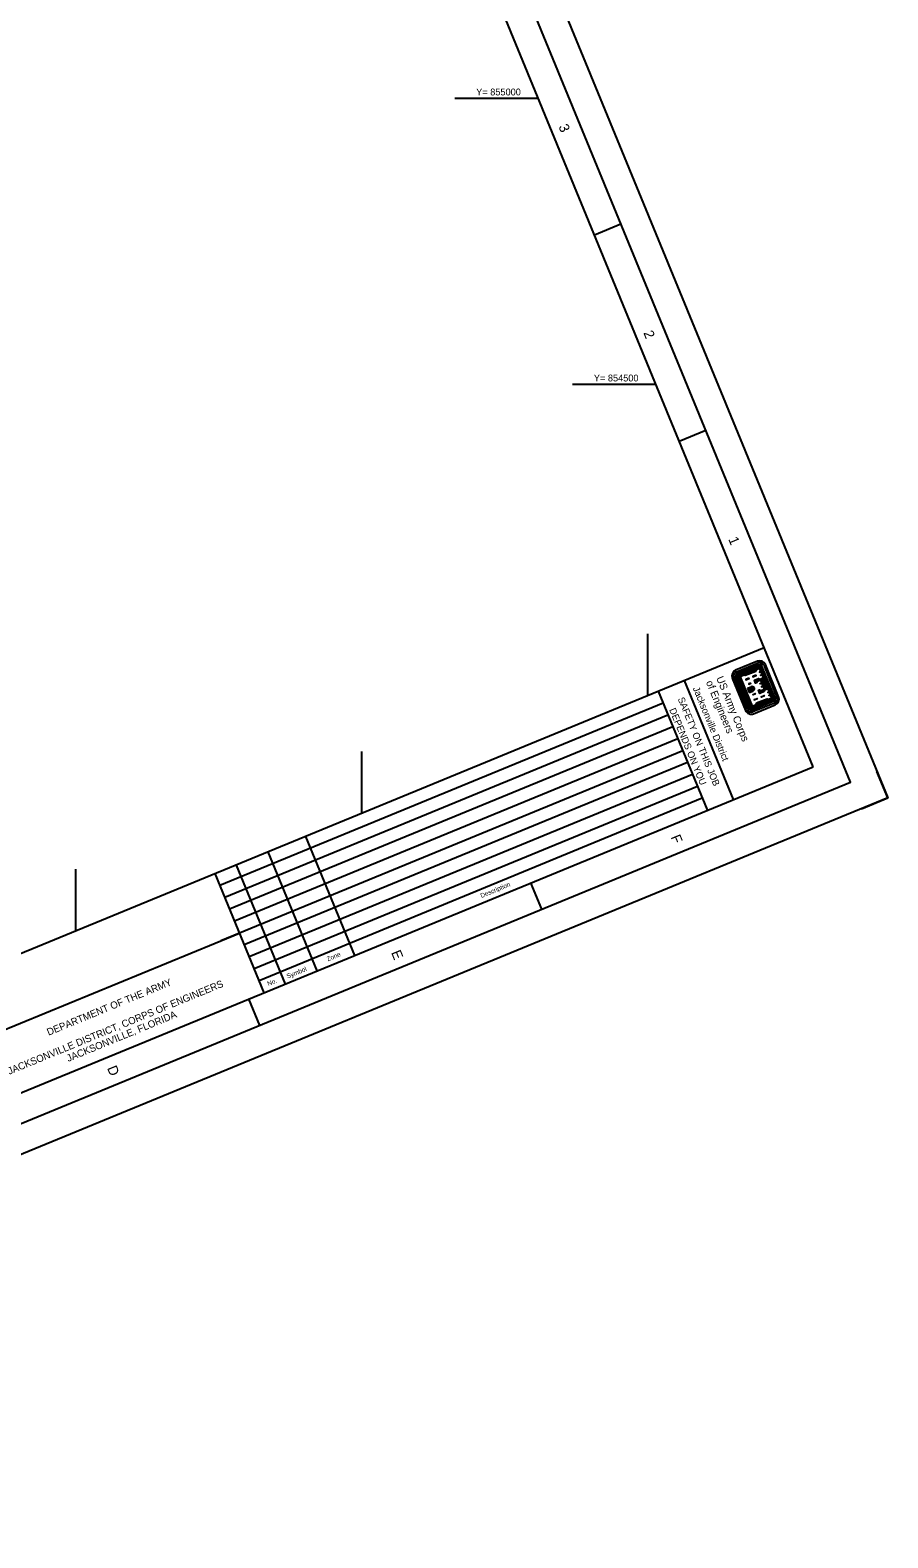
# Model space of a CAD drawing. Extents: x 579601 to 584420, y 852483 to 857846.
# Drawn here: x 582920 to 584420, y 852483 to 855119 of the extents above; entities that cross this region are included whole.
import ezdxf

# ---------------------------------------------------------------- set-up
doc = ezdxf.new("R2010")
doc.units = 0
for name, color, linetype in [('G-ANNO-NPLT', 7, 'Continuous'), ('G-ANNO-TEXT-LOGO', 7, 'Continuous'), ('G-ANNO-TEXT-TTLB', 7, 'Continuous'), ('G-ANNO-TTLB', 7, 'Continuous'), ('V-TOPO-COOR-STAT', 7, 'Continuous')]:
    doc.layers.add(name, color=color, linetype=linetype)

msp = doc.modelspace()

# ---------------------------------------------------------------- linework, layer by layer
at = {"layer": 'G-ANNO-NPLT'}
msp.add_lwpolyline([(582745.7, 857846.1), (584419.8, 853777), (581275.5, 852483.4), (579601.4, 856552.5)], close=True, dxfattribs=at)
msp.add_lwpolyline([(584373.5, 853758), (584419.8, 853777), (584400.7, 853823.2)], dxfattribs=at)
at = {"layer": 'G-ANNO-TEXT-LOGO'}
for p, q in [((584191.7, 854015.8), (584153.7, 854000.2)), ((584155, 853997.2), (584192.9, 854012.8)), ((584194.2, 854009.6), (584156.3, 853994)), ((584194.5, 854008.8), (584156.6, 853993.2)), ((584194.8, 854008), (584156.9, 853992.4)), ((584195.2, 854007.2), (584157.3, 853991.6)), ((584195.5, 854006.4), (584157.6, 853990.8)), ((584195.9, 854005.5), (584158.2, 853990.1)), ((584196.2, 854004.8), (584159.4, 853989.7)), ((584188.4, 854000.8), (584169, 853992.9)), ((584187.9, 853999.7), (584170.2, 853992.4)), ((584219.4, 853949.9), (584196.3, 854006.1)), ((584220.2, 853950.3), (584197.1, 854006.5)), ((584221, 853950.6), (584197.9, 854006.8)), ((584221.8, 853950.9), (584198.7, 854007.1)), ((584222.6, 853951.2), (584199.5, 854007.5)), ((584202.7, 854008.8), (584225.8, 853952.5)), ((584228.8, 853953.8), (584205.6, 854010)), ((584147.8, 853986.2), (584171, 853930)), ((584174, 853931.2), (584150.9, 853987.5)), ((584177.2, 853932.6), (584154.1, 853988.8)), ((584178, 853932.9), (584154.8, 853989.1)), ((584178.8, 853933.2), (584155.7, 853989.4)), ((584179.6, 853933.6), (584156.5, 853989.8)), ((584180.4, 853933.9), (584157.3, 853990.1)), ((584181.1, 853934.6), (584158.2, 853990.1)), ((584181.6, 853935.6), (584159.4, 853989.7)), ((584174.4, 853968.6), (584180.6, 853971.1)), ((584198.8, 853984.3), (584205.8, 853967.1)), ((584199.6, 853984.7), (584206.7, 853967.5)), ((584200.3, 853985), (584207.4, 853967.8)), ((584201.2, 853985.3), (584208.2, 853968.1)), ((584202, 853985.7), (584209.1, 853968.5)), ((584202.7, 853986), (584209.8, 853968.8)), ((584203.6, 853986.3), (584210.6, 853969.1)), ((584174.4, 853968.6), (584177.5, 853961.2)), ((584174.7, 853967.9), (584180.9, 853970.4)), ((584175.1, 853967), (584181.3, 853969.6)), ((584175.4, 853966.2), (584181.6, 853968.7)), ((584175.7, 853965.5), (584181.9, 853968)), ((584176.2, 853964.3), (584182.4, 853966.9)), ((584176.5, 853963.6), (584182.7, 853966.2)), ((584176.8, 853962.8), (584183, 853965.3)), ((584177.2, 853961.9), (584183.4, 853964.5)), ((584177.5, 853961.2), (584183.7, 853963.7)), ((584218.7, 853950.1), (584181.1, 853934.6)), ((584219, 853949.2), (584181.1, 853933.6)), ((584219.4, 853948.4), (584181.5, 853932.8)), ((584218.4, 853950.8), (584181.6, 853935.6)), ((584219.7, 853947.6), (584181.8, 853932)), ((584220, 853946.8), (584182.1, 853931.2)), ((584220.4, 853946), (584182.5, 853930.4)), ((584210, 853948.1), (584190.8, 853940.2)), ((584208.9, 853948.6), (584191.2, 853941.4)), ((584221.7, 853942.8), (584183.8, 853927.2)), ((584185, 853924.2), (584222.9, 853939.8))]:
    msp.add_line(p, q, dxfattribs=at)
for points in [[(584196.4, 854004.2), (584189.1, 854001.1), (584188.2, 853998.9), (584170.6, 853991.7), (584168.2, 853992.5), (584160.2, 853989.2), (584181.9, 853936.5), (584189.9, 853939.8), (584190.9, 853942.2), (584208.6, 853949.5), (584210.8, 853948.4), (584218.1, 853951.4), (584215.3, 853958.4), (584213.1, 853963.7), (584211, 853968.7), (584203.7, 853965.7), (584202.9, 853963.3), (584196.4, 853960.7), (584194.8, 853964.5), (584195.4, 853964.8), (584197.8, 853963.8), (584205, 853966.8), (584202.1, 853973.7), (584199.9, 853979.1), (584197.9, 853984), (584190.7, 853981), (584189.7, 853978.7), (584189.1, 853978.4), (584187.5, 853982.3), (584194, 853985), (584196.2, 853983.9), (584203.5, 853987), (584200.7, 853993.9), (584198.5, 853999.3), (584196.4, 854004.2)], [(584195.9, 854003.1), (584189.8, 854000.6), (584188.8, 853998.2), (584170.5, 853990.7), (584168.2, 853991.7), (584161.3, 853988.8), (584182.4, 853937.6), (584189.3, 853940.4), (584190.2, 853942.9), (584208.5, 853950.4), (584210.9, 853949.3), (584217, 853951.8), (584214.9, 853956.8), (584212.1, 853955.7), (584211.9, 853956.1), (584214.8, 853957.3), (584212.7, 853962.2), (584209.9, 853961), (584209.7, 853961.4), (584212.6, 853962.6), (584210.5, 853967.6), (584204.4, 853965), (584203.4, 853962.7), (584196, 853959.6), (584193.7, 853965), (584195.5, 853965.7), (584197.9, 853964.7), (584204, 853967.2), (584201.9, 853972.2), (584199, 853971), (584198.9, 853971.4), (584201.8, 853972.6), (584199.7, 853977.6), (584196.8, 853976.4), (584196.6, 853976.9), (584199.5, 853978.1), (584197.5, 853983), (584191.4, 853980.4), (584190.4, 853978.1), (584188.6, 853977.4), (584186.4, 853982.7), (584193.9, 853985.8), (584196.3, 853984.8), (584202.4, 853987.3), (584200.4, 853992.3), (584197.5, 853991.1), (584197.3, 853991.5), (584200.2, 853992.7), (584198.1, 853997.7), (584195.3, 853996.5), (584195.1, 853996.9), (584198, 853998.1), (584195.9, 854003.1)], [(584176.8, 853986.4), (584171.4, 853984.1), (584171.6, 853983.6), (584177.1, 853985.8), (584176.8, 853986.4)], [(584180.3, 853977.8), (584176.6, 853976.3), (584176.7, 853975.8), (584180.5, 853977.4), (584180.3, 853977.8)], [(584189.1, 853991.4), (584183.8, 853989.2), (584184, 853988.7), (584189.4, 853990.9), (584189.1, 853991.4)], [(584194.6, 853983.7), (584193.9, 853984), (584188.7, 853981.8), (584189.4, 853980.1), (584190.1, 853981.7), (584194.7, 853983.7)], [(584188.2, 853958.8), (584184.4, 853957.2), (584184.2, 853957.7), (584188, 853959.3), (584188.2, 853958.8)], [(584191.6, 853950.4), (584186.2, 853948.1), (584186, 853948.6), (584191.5, 853950.8), (584191.6, 853950.4)], [(584202.4, 853964.7), (584202.2, 853964), (584196.9, 853961.8), (584196.2, 853963.5), (584197.9, 853962.9), (584202.5, 853964.8)], [(584203.9, 853955.4), (584198.6, 853953.2), (584198.4, 853953.7), (584203.8, 853955.9), (584203.9, 853955.4)]]:
    msp.add_lwpolyline(points, dxfattribs=at)
for centre, major_axis, start_param, end_param in [((584157.8, 853990.3), (-4.08, 9.91), 6.28317, 7.853966), ((584157.8, 853990.3), (-2.85, 6.93), 6.28317, 7.853966), ((584195.7, 854005.9), (4.08, -9.91), 1.57078, 3.141576), ((584195.7, 854005.9), (2.85, -6.93), 1.57078, 3.141576), ((584195.7, 854005.9), (1.53, -3.72), 1.57078, 3.141576), ((584195.7, 854005.9), (1.2, -2.91), 1.57078, 3.141576), ((584195.7, 854005.9), (0.87, -2.11), 1.57078, 3.141576), ((584195.7, 854005.9), (0.54, -1.31), 1.57078, 3.141576), ((584195.7, 854005.9), (0.208, -0.505), 1.57078, 3.141576), ((584157.8, 853990.3), (-1.53, 3.72), 6.28317, 7.853966), ((584157.8, 853990.3), (-1.2, 2.91), 6.28317, 7.853966), ((584157.8, 853990.3), (-0.87, 2.11), 6.28317, 7.853966), ((584157.8, 853990.3), (-0.54, 1.31), 6.28317, 7.853966), ((584157.8, 853990.3), (-0.208, 0.505), 6.28317, 7.853966), ((584182.3, 853965.9), (-2.11, 5.14), 4.985832, 6.214359), ((584182.3, 853965.9), (-1.78, 4.33), 4.947465, 6.21436), ((584182.3, 853965.9), (-1.45, 3.53), 4.947465, 6.21436), ((584182.3, 853965.9), (-1.12, 2.73), 4.947465, 6.21436), ((584182.3, 853965.9), (-0.79, 1.92), 4.947465, 6.214359), ((584181.1, 853968.7), (0.79, -1.92), 0.068794, 1.335689), ((584181.1, 853968.7), (1.12, -2.73), 0.068794, 1.335689), ((584181.1, 853968.7), (1.45, -3.53), 0.068795, 1.335689), ((584181.1, 853968.7), (1.78, -4.33), 0.068795, 1.335689), ((584181.1, 853968.7), (2.11, -5.14), 0.068795, 1.29842), ((584218.8, 853949.7), (0.208, -0.505), 6.283169, 7.853965), ((584218.8, 853949.7), (0.54, -1.31), 6.283169, 7.853965), ((584218.8, 853949.7), (0.87, -2.11), 6.283169, 7.853965), ((584218.8, 853949.7), (1.2, -2.91), 6.283169, 7.853965), ((584218.8, 853949.7), (1.53, -3.72), 6.283169, 7.853965), ((584218.8, 853949.7), (2.85, -6.93), 6.28317, 7.853966), ((584218.8, 853949.7), (4.08, -9.91), 6.283169, 7.853965), ((584180.9, 853934.1), (4.08, -9.91), 4.712373, 6.28317), ((584180.9, 853934.1), (-2.85, 6.93), 1.570781, 3.141577), ((584180.9, 853934.1), (1.53, -3.72), 4.712373, 6.28317), ((584180.9, 853934.1), (1.2, -2.91), 4.712373, 6.28317), ((584180.9, 853934.1), (0.87, -2.11), 4.712373, 6.28317), ((584180.9, 853934.1), (0.54, -1.31), 4.712373, 6.28317), ((584180.9, 853934.1), (0.208, -0.505), 4.712373, 6.28317)]:
    msp.add_ellipse(centre, major_axis=major_axis, ratio=0.99964, start_param=start_param, end_param=end_param, dxfattribs=at)
at = {"layer": 'G-ANNO-TTLB'}
for p, q in [((583953.1, 854779.9), (583906.9, 854760.8)), ((584101.5, 854419.2), (584055.2, 854400.2)), ((584203.6, 854039.5), (581244.3, 852822)), ((584063.8, 853982), (584149.4, 853773.9)), ((584018.1, 853963.8), (584103.7, 853755.8)), ((584026.8, 853942.6), (583251.9, 853623.8)), ((584035.4, 853921.8), (583260.5, 853603)), ((584043.9, 853901), (583269.1, 853582.2)), ((584052.5, 853880.2), (583277.6, 853561.4)), ((584061.1, 853859.4), (583286.2, 853540.6)), ((584069.6, 853838.6), (583294.7, 853519.8)), ((584078.2, 853817.8), (583303.3, 853499)), ((584086.8, 853797), (583311.9, 853478.2)), ((584095.3, 853776.2), (583320.4, 853457.4)), ((583401.6, 853709.5), (583487.2, 853501.5)), ((583335.8, 853682.5), (583421.4, 853474.4)), ((583280.3, 853659.6), (583365.9, 853451.5)), ((583243.4, 853644.5), (583329, 853436.4)), ((583814.9, 853582.2), (583795.9, 853628.4)), ((582491.1, 853214), (583286.2, 853540.4)), ((583286.2, 853540.4), (583253.5, 853527)), ((583321.7, 853379.3), (583302.7, 853425.5))]:
    msp.add_line(p, q, dxfattribs=at)
for points in [[(579666.7, 856525.2), (581302.7, 852548.7), (584354.5, 853804.2), (582718.5, 857780.8)], [(584289.2, 853831.4), (582719.8, 857646.2), (579760.5, 856428.7), (581329.9, 852613.9)]]:
    msp.add_lwpolyline(points, close=True, dxfattribs=at)
at = {"layer": 'V-TOPO-COOR-STAT'}
for p, q in [((583662.5, 855000), (583808.5, 855000)), ((583868.2, 854500), (584014.2, 854500)), ((584000, 853955.8), (584000, 854063.9)), ((583500, 853750), (583500, 853858.2)), ((583000, 853544.3), (583000, 853652.5))]:
    msp.add_line(p, q, dxfattribs=at)

# ---------------------------------------------------------------- texts
at = {"layer": 'G-ANNO-TEXT-TTLB'}
for s, height, rotation, p in [('of Engineers', 13.086, 292.363, (584101.5, 853979.2)), ('US Army Corps', 13.086, 292.363, (584119.5, 853986.5)), ('SAFETY ON THIS JOB', 11.9, 292.363, (584052.2, 853950.1)), ('Jacksonville District', 11.9, 292.363, (584078.5, 853968.6)), ('DEPENDS ON YOU', 11.9, 292.363, (584037.3, 853931.2)), ('Description', 8, 22.363, (583709.4, 853601.9)), ('Zone', 8, 22.363, (583440.7, 853491.1)), ('Symbol', 8, 22.363, (583370.5, 853460.9)), ('JACKSONVILLE DISTRICT, CORPS OF ENGINEERS', 12.5, 22.363, (582884, 853292.9)), ('DEPARTMENT OF THE ARMY', 12.5, 22.363, (582952.6, 853361.1)), ('No.', 8, 22.363, (583336.8, 853448.1)), ('JACKSONVILLE, FLORIDA', 12.5, 22.363, (582987.1, 853315.3))]:
    msp.add_text(s, height=height, rotation=rotation, dxfattribs=at).set_placement(p)
at = {"layer": 'G-ANNO-TTLB'}
for s, p in [('3', (583843.7, 854950.7)), ('2', (583992.1, 854590)), ('1', (584140.5, 854229.4)), ('F', (584039.9, 853708.5)), ('E', (583551.1, 853506.6)), ('D', (583054.5, 853304.7))]:
    msp.add_text(s, height=17.5, rotation=292.363, dxfattribs=at).set_placement(p)
at = {"layer": 'V-TOPO-COOR-STAT'}
for s, p in [('Y= 855000', (583700.1, 855005)), ('Y= 854500', (583905.8, 854505))]:
    msp.add_text(s, height=12, dxfattribs=at).set_placement(p)

doc.saveas('drawing.dxf')
